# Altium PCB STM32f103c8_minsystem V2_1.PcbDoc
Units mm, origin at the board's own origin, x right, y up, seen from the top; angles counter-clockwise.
Board outline 18 x 35 mm, 2 copper layers (Top Layer, Bottom Layer); 27 components, 47 nets, 152 pads, 125 vias.
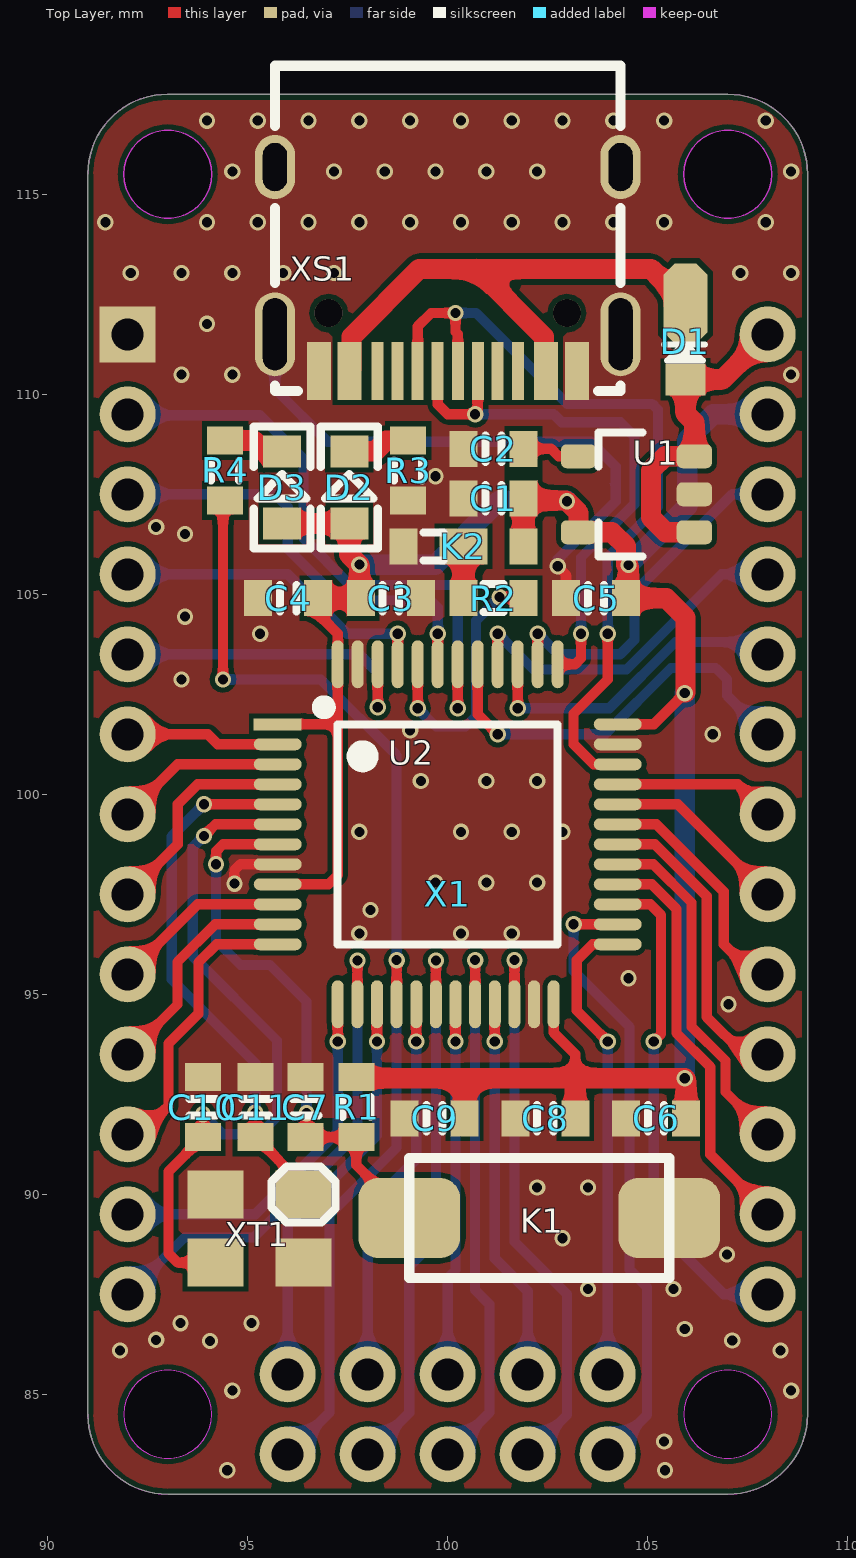
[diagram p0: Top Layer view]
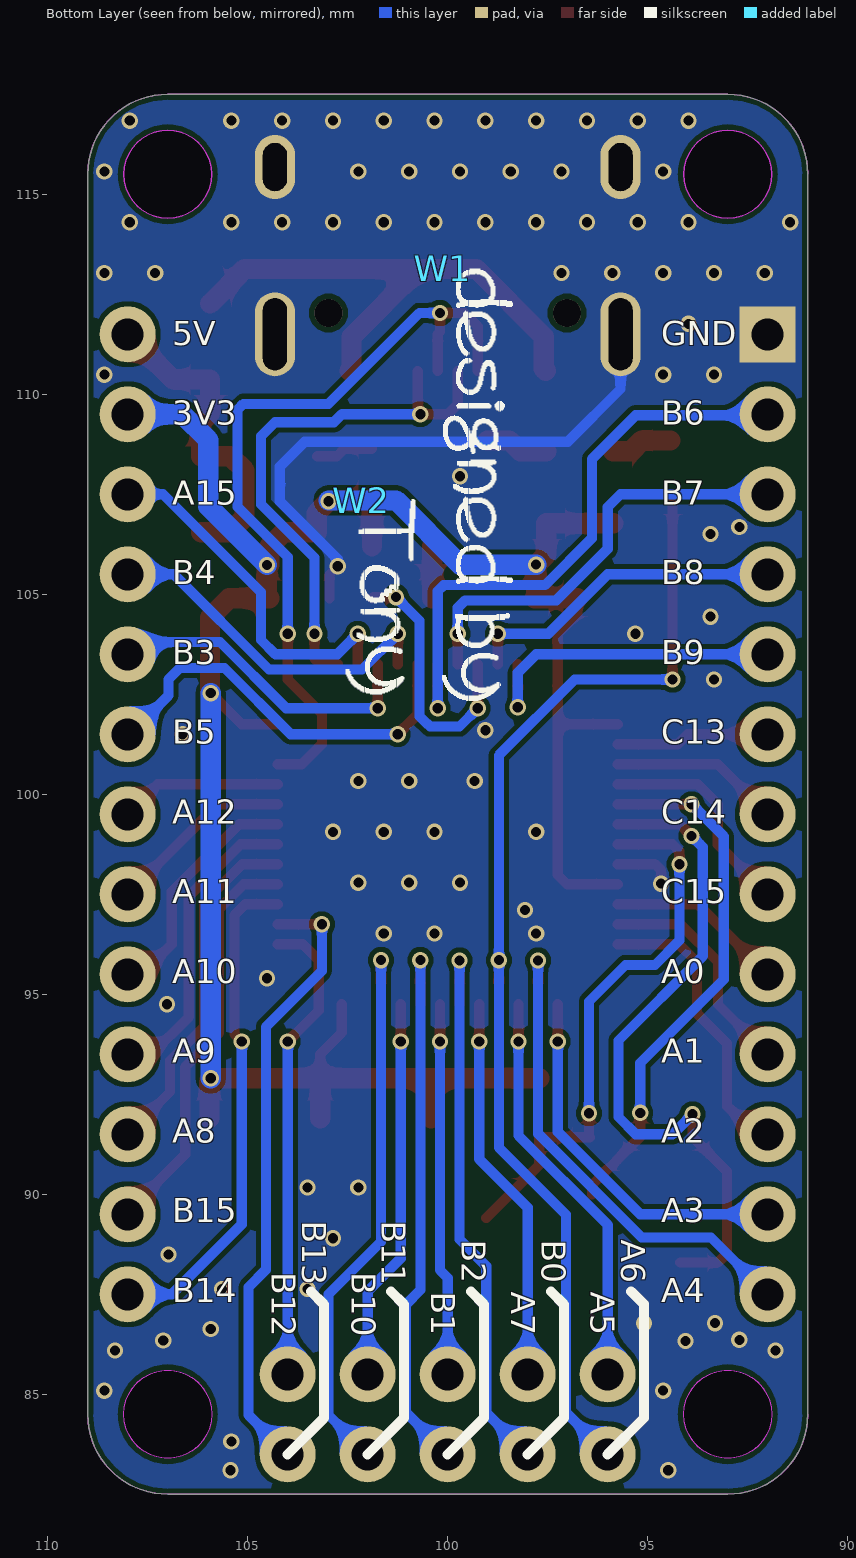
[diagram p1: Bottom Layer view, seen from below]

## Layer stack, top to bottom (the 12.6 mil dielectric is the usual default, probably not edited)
Top Solder: solder mask 0.0102, Solder Resist, Dk 3.5
Top Layer: signal copper 0.0356
Dielectric 1: dielectric 0.32, FR-4, Dk 4.8
Bottom Layer: signal copper 0.0356
Bottom Solder: solder mask 0.0102, Solder Resist, Dk 3.5

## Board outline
91,84.5 91,115.5 cw(c93,115.5) 93,117.5 107,117.5 cw(c107,115.5) 109,115.5 109,84.5 cw(c107,84.5) 107,82.5 93,82.5 cw(c93,84.5)
cut-out: 93,114.4 cw(c93,115.5) 91.9,115.5 cw(c93,115.5) 93,116.6 cw(c93,115.5) 94.1,115.5 cw(c93,115.5)
cut-out: 107,114.4 cw(c107,115.5) 105.9,115.5 cw(c107,115.5) 107,116.6 cw(c107,115.5) 108.1,115.5 cw(c107,115.5)
cut-out: 91.9,84.5 ccw(c93,84.5) 93,83.4 ccw(c93,84.5) 94.1,84.5 ccw(c93,84.5) 93,85.6 ccw(c93,84.5)
cut-out: 105.9,84.5 ccw(c107,84.5) 107,83.4 ccw(c107,84.5) 108.1,84.5 ccw(c107,84.5) 107,85.6 ccw(c107,84.5)

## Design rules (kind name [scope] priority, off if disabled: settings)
Clearance [All] p1: gap=0.127 ignorepadtopadclearanceinfootprint=TRUE
ComponentClearance [All] p1 off: gap=0 collisioncheckmode=3 verticalgap=0.254 showdistances=FALSE
PlaneConnect [All] p1: planeconnectstyle=Direct reliefexpansion=0.508 reliefentries=4 reliefconductorwidth=0.254 reliefairgap=0.254
PolygonConnect PolygonConnect_3 [All vs IsNamedPolygon('GND_L01_P001')] p1: connectstyle=Direct reliefconductorwidth=0.254 reliefentries=4 polygonreliefangle="90 Angle" airgapwidth=0.254
PolygonConnect PolygonConnect_2 [All vs IsNamedPolygon('GND_L02_P000')] p2: connectstyle=Direct reliefconductorwidth=0.254 reliefentries=4 polygonreliefangle="90 Angle" airgapwidth=0.254
PolygonConnect [All vs IsNamedPolygon('Bottom Layer-GND')] p3: connectstyle=Direct reliefconductorwidth=0.508 reliefentries=4 polygonreliefangle="90 Angle" airgapwidth=0.254
PolygonConnect PolygonConnect_1 [All vs IsNamedPolygon('Top Layer-GND')] p4: connectstyle=Direct reliefconductorwidth=0.508 reliefentries=4 polygonreliefangle="90 Angle" airgapwidth=0.254
RoutingVias [All] p1: holewidth=0.254 width=0.406 viastyle="Through Hole" minholewidth=0.254 minwidth=0.406 maxholewidth=0.711 maxwidth=1.27
SolderMaskExpansion [All] p1: expansion=0.102 istentingtop=FALSE
Width [All] p1: maxlimit=2.54 minlimit=0.254 preferedwidth=0.254
28 further rules are at their usual default settings.

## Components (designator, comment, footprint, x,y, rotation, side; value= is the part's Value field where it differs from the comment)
C1 "106" CAP_0603 101.143,107.779 r0 top locked
C2 "106" CAP_0603 101.143,109.017 r0 top locked
C3 "104" CAP_0603 98.577,104.521 r180 top locked
C4 "104" CAP_0603 96.012,104.521 r180 top locked
C5 "104" CAP_0603 103.708,105.283 r0 top locked
C6 "104" CAP_0603 105.207,92.278 r0 top locked
C7 "104" CAP_0603 96.063,92.177 r90 top locked
C8 "104" CAP_0603 102.438,92.278 r0 top locked
C9 "105" CAP_0603 99.67,92.278 r0 top locked
C10 "22p" CAP_0603 93.497,92.177 r90 top locked
C11 "22p" CAP_0603 94.818,92.177 r90 top locked
D1 "ss14" SOD-323 105.943,110.368 r90 top locked
D2 "led" led0603 97.663,107.721 r90 top locked
D3 "led" led0603 95.987,107.721 r90 top locked
K1 "3-6微动开关" 3-6微动开关 105.537,89.408 r180 top locked
K2 "Boot0选择-默认GND" "Switch 1-2 0603" 98.893,106.197 r0 top locked
R1 "10k" RES_0603 98.095,92.177 r270 top locked
R2 "10k" RES_0603 101.143,105.283 r0 top locked
R3 "3k" RES_0603 99.39,108.095 r270 top locked
R4 "3k" RES_0603 94.818,108.095 r270 top locked
U1 "ME6211 3V3" SOT23-5 104.667,107.5 r180 top locked
U2 "STM32F103C8T6" LQFP48 100,99 r0 top locked
W1 "设计于" "designed by（430-70）" 100.129,113.132 r270 bottom
W2 "Tony" Tony_2(200-70) 102.158,107.345 r270 bottom
X1 "STM32F103C8T6模块接口 V2.1" "STM32F103C8T6 V2_1引脚" 90,111.5 r0 top locked
XS1 "Type-C" TypeC-304-16BCP 95.68,111.5 r180 top locked
XT1 "8M" SMD3225_4p 96.393,89.99 r180 top locked

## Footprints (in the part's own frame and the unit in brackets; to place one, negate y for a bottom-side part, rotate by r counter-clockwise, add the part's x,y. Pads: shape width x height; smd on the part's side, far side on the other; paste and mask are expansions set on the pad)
3-6微动开关 [mm]
  rrect50% 2.54x2 smd: 1(0,0) 2(6.5,0)
  silkscreen extent 0,-1.5 6.5,1.5, body extent -0.9,-1.78 7.1,1.72, height 2.59
CAP_0603 [mm]
  rect 0.7x0.9 smd: 1(-0.75,-0.381) 2(0.75,-0.381)
  silkscreen extent -0.2,-0.71 0.2,-0.05, body extent -0.8,-0.78 0.8,0.02, height 0.8
"designed by（430-70）" [mm]
  silkscreen extent 0,0 10.79,1.75
led0603 [mm]
  rect 0.8x0.95 smd: 1(-0.95,0.125) 2(0.85,0.125)
  silkscreen extent -1.57,-0.59 1.47,0.84, body extent -1.02,-0.4 1,0.67, height 0.5
LQFP48 [mm] "STM32-48pin"
  rect 1.2x0.3 smd mask+0.051: 1(-4.25,2.75)
  oval 1.2x0.3 smd mask+0.051: 2(-4.25,2.25) 3(-4.25,1.75) 4(-4.25,1.25) 5(-4.25,0.75) 6(-4.25,0.25) 7(-4.25,-0.25) 8(-4.25,-0.75) 9(-4.25,-1.25) 10(-4.25,-1.75) 11(-4.25,-2.25) 12(-4.25,-2.75) 25(4.25,-2.75) 26(4.25,-2.25) 27(4.25,-1.75) 28(4.25,-1.25) 29(4.25,-0.75) 30(4.25,-0.25) 31(4.25,0.25) 32(4.25,0.75) 33(4.25,1.25) 34(4.25,1.75) 35(4.25,2.25) 36(4.25,2.75)
  oval 0.3x1.2 smd mask+0.051: 13(-2.75,-4.25) 14(-2.259,-4.25) 15(-1.768,-4.25) 16(-1.278,-4.25) 17(-0.787,-4.25) 18(-0.296,-4.25) 19(0.195,-4.25) 20(0.685,-4.25) 21(1.176,-4.25) 22(1.667,-4.25) 23(2.158,-4.25) 24(2.648,-4.25) 37(2.75,4.25) 38(2.25,4.25) 39(1.75,4.25) 40(1.25,4.25) 41(0.75,4.25) 42(0.25,4.25) 43(-0.25,4.25) 44(-0.75,4.25) 45(-1.25,4.25) 46(-1.75,4.25) 47(-2.25,4.25) 48(-2.75,4.25)
  silkscreen extent -3.25,-2.75 2.75,3.32, body extent -4.5,-4.5 4.5,4.5, height 1.45
RES_0603 [mm]
  rect 0.7x0.9 smd: 1(-0.75,-0.381) 2(0.75,-0.381)
  silkscreen extent -0.25,-0.73 0.25,-0.03, body extent -0.8,-0.78 0.8,0.02, height 0.45
SMD3225_4p [mm]
  rect 1.4x1.2 smd: 1(0,0) 2(2.2,0) 3(2.2,1.7) 4(0,1.7)
  silkscreen extent -0.8,-0.7 0.8,0.7, body extent -0.51,-0.41 2.69,2.09, height 0.81
SOD-323 [mm] "1.8x1.3X0.9mm（长宽高，不包括引脚）"
  oct 2x1.1 smd: 1(1.9,0)
  rect 0.8x1 smd: 2(0,0)
  silkscreen extent 0.47,-0.48 0.88,0.53, body extent -0.15,-0.67 2.5,0.62, height 1
SOT23-5 [mm] "SOT23, 3-Leads, Body 3.1x3.0mm (max), Pitch 0.95mm, IPC Medium Density"
  rrect50% 0.889x0.6 smd: 1(-1.5,0.95) 2(-1.5,0) 3(-1.5,-0.95) 4(1.396,-0.95) 5(1.396,0.95)
  silkscreen extent -0.2,-1.55 0.9,1.55, body extent -1.48,-1.45 1.32,1.45, height 1.2
"STM32F103C8T6 V2_1引脚" [mm] "排针朝下"
  rect 1.4x1.4 hole 0.8: 1(2,0)
  round 1.4 hole 0.8: 2(2,-2) 3(2,-4) 4(2,-6) 5(2,-8) 6(2,-10) 7(2,-12) 8(2,-14) 9(2,-16) 10(2,-18) 11(2,-20) 12(2,-22) 13(2,-24) 14(6,-26) 15(6,-28) 16(8,-26) 17(8,-28) 18(10,-26) 19(10,-28) 20(12,-26) 21(12,-28) 22(14,-26) 23(14,-28) 24(18,-24) 25(18,-22) 26(18,-20) 27(18,-18) 28(18,-16) 29(18,-14) 30(18,-12) 31(18,-10) 32(18,-8) 33(18,-6) 34(18,-4) 35(18,-2) 36(18,0)
  body extent 1,-29 19,1, height 1.8
"Switch 1-2 0603" [mm] "单刀双掷0603贴片选择开关"
  rect 0.7x0.9 smd: 1(0,0) 3(3,0)
  rect 1.2x0.9 smd: 2(1.5,0)
  silkscreen extent 0.5,-0.35 1,0.35, body extent -0.05,-0.4 1.55,0.4, height 0.45
Tony_2(200-70) [mm]
  silkscreen extent -0.03,-0.38 4.85,1.35
TypeC-304-16BCP [mm]
  oval 1x2.1 hole 0.6 slot 1.8 at 90 deg: 13(-8.64,0) 14(0,0)
  oval 1x1.6 hole 0.6 slot 1.2 at 90 deg: 15(-8.64,-4.18) 16(0,-4.18)
  rect 0.6x1.45 smd: A1B12(-7.545,0.915) A4B9(-6.77,0.915) B1A12(-1.1,0.915) B4A9(-1.87,0.915)
  rect 0.3x1.45 smd: A5(-5.57,0.914) A6(-4.57,0.915) A7(-4.07,0.915) A8(-3.07,0.915) B5(-2.57,0.915) B6(-3.57,0.915) B7(-5.07,0.915) B8(-6.07,0.915)
  round 0.7 hole 0.7 unplated: ""(-7.3,-0.53) ""(-1.34,-0.53)
  silkscreen extent -8.64,-6.71 0,1.42, body extent -8.77,-6.9 0.17,1, height 3.11

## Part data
C1 C2 C3 C4 C5 C6 C7 C8 C9 C10 C11: library part cap
D1: library part Diode
K1: "3*6mm"
K2: library part "Switch 1-2", "单刀双掷1-2"
R1 R2 R3 R4: library part Res
U1: library part ME6211, "LDO"
U2: library part STM32F103C8T6-LCC
XS1: library part Type-C母口
XT1: library part XTAL-4P

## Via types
v1: diameter 0.406, hole 0.254, Top Layer to Bottom Layer, 65 vias
v2: diameter 0.406, hole 0.254, Top Layer to Bottom Layer, tented both sides, 60 vias

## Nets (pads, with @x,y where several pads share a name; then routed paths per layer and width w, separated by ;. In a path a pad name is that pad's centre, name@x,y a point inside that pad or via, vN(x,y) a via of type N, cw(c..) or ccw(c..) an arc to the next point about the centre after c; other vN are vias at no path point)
3v3: C1.2 C3.2 C4.1 C5.2 C6.2 C8.2 C9.2 D2.1 D3.1 K2.3 R1.1 U1.5 U2.1 U2.9 U2.24 U2.36 U2.48 X1.35 | length 61.2
  Top Layer w0.254: U2.9 97.02,97.75 97.25,97.98 97.25,101.75 ; U2.1 97.25,101.75 ; C4.1 96.762,104.501 97.25,104.013 U2.48 97.25,101.75 ; U2.24 102.648,94.04 103.188,93.5 103.188,92.901 103.188,92.864 ; U2.36 105.148,101.75 v2(105.926,102.527) v2@105.943,102.545
  Top Layer w0.508: D3.1 D2.1 97.538,105.993 v2(97.79,105.74) 97.79,104.939 C3.2 C4.1 ; R1.1@97.714,92.901 100.432,92.901 ; C9.2 100.432,91.909 100.432,92.901 ; K2.3 C1.2 101.946,107.345 102.958,107.345 103.271,107.032 U1.5 104.106,106.55 104.458,106.197 v2@104.458,105.74 ; C8.2 103.188,92.864 ; v2(104.517,105.731) 104.517,104.961 C5.2 105.461,104.902 105.943,104.419 v2@105.943,102.545 ; C6.2 105.957,92.87 v2(105.926,92.901) 103.188,92.901 100.432,92.901
  Bottom Layer w0.508: v2(97.79,105.74) 99.688,105.74 101.293,107.345 v2@102.98,107.345 ; v2(104.517,105.731) 105.99,107.203 105.99,108.857 106.633,109.5 X1.35 ; v2(105.926,92.901) v2(105.926,102.527)
  other v2: 102.98,107.323
BOOT0: R2.2 U2.44 | length 6.7
  Top Layer w0.254: v2(99.25,102.151) U2.44 ; v2(101.295,104.927) 101.867,104.927 R2.2
  Bottom Layer w0.254: v2(99.25,102.151) 99.707,101.694 100.439,101.694 100.498,101.752 100.508,101.752 100.707,101.952 100.707,104.339 v2(101.295,104.927)
GND: C1.1 C2.1 C3.1 C4.2 C5.1 C6.1 C7.2 C8.1 C9.1 C10.2 C11.2 K1.1 K2.1 R3.2 U1.2 U2.8 U2.23 U2.35 U2.47 X1.1 XS1.13 XS1.14 XS1.15 XS1.16 XS1.A1B12 XS1.B1A12 XT1.2 XT1.4 | length 16.1
  Top Layer w0.254: v2(94.666,97.765) 94.666,98.101 94.815,98.25 U2.8 ; v2(102.75,105.7) 102.958,105.492 C5.1
  Bottom Layer w0.254: XS1.14 95.68,110.132 96.999,108.814 103.574,108.814 104.199,108.188 104.199,107.323 102.75,105.874 v2(102.75,105.7)
  other v1: 105.41,83.82 94.615,85.09 108.585,85.09 92.71,86.36 103.505,87.63 102.87,88.9 102.235,90.17 103.505,90.17 97.79,96.52 100.33,96.52 101.6,96.52 99.695,97.79 100.965,97.79 102.235,97.79 97.79,99.06 100.33,99.06 101.6,99.06 102.87,99.06 100.965,100.33 102.235,100.33 99.06,101.6 93.345,102.87 92.71,106.68 99.695,107.95 93.345,110.49 94.615,110.49 108.585,110.49 93.98,111.76 92.075,113.03 93.345,113.03 94.615,113.03 95.885,113.03 97.155,113.03 107.315,113.03 108.585,113.03 91.44,114.3 93.98,114.3 95.25,114.3 96.52,114.3 97.79,114.3 99.06,114.3 100.33,114.3 101.6,114.3 102.87,114.3 104.14,114.3 105.41,114.3 107.95,114.3 94.615,115.57 97.155,115.57 98.425,115.57 99.695,115.57 100.965,115.57 102.235,115.57 108.585,115.57 93.98,116.84 95.25,116.84 96.52,116.84 97.79,116.84 99.06,116.84 100.33,116.84 101.6,116.84 102.87,116.84 104.14,116.84 105.41,116.84 107.95,116.84
  other v2: 94.489,83.1 105.43,83.1 91.806,86.096 108.319,86.096 94.058,86.334 107.112,86.346 105.926,86.628 93.321,86.778 95.095,86.778 105.643,87.63 106.984,88.494 107.017,94.75 104.517,95.4 98.071,97.108 99.327,100.334 106.627,101.5 95.31,104.013 93.433,104.44 93.433,106.506
NetC2_2: C2.2 U1.4 | length 1.5
  Top Layer w0.254: C2.2 102.584,108.636 102.77,108.45 U1.4
NetC10_1: C10.1 U2.6 XT1.3 | length 17.3
  Top Layer w0.254: v2(93.878,91.999) C10.1 93.016,90.564 93.016,88.524 93.25,88.29 XT1.3 ; v2(93.904,98.958) 94.195,99.25 U2.6
  Bottom Layer w0.254: v2(93.878,91.999) 94.377,91.5 95.301,91.5 95.733,91.932 95.733,93.844 93.624,95.952 93.624,98.679 v2(93.904,98.958)
NetC11_1: C11.1 U2.5 XT1.1 | length 13.3
  Top Layer w0.254: v2(93.904,99.75) U2.5 ; v2(95.189,92.035) 95.189,91.437 96.393,90.233 XT1.1
  Bottom Layer w0.254: v2(93.904,99.75) 93.1,98.946 93.1,95.368 95.189,93.279 v2(95.189,92.035)
NetD1_1: D1.1 XS1.A4B9 XS1.B4A9 | length 13.5
  Top Layer w0.508: XS1.B4A9 97.596,110.631 97.596,111.437 99.29,113.132 100.708,113.132 ; XS1.A4B9 102.404,110.631 102.404,111.436 100.708,113.132 ; D1.1 105.08,113.132 100.708,113.132
NetD2_2: D2.2 R3.1 | length 1.6
  Top Layer w0.508: D2.2 98.185,108.571 98.459,108.845 R3.1
NetD3_2: D3.2 R4.1 | length 1.5
  Top Layer w0.508: R4.1 95.15,108.845 95.424,108.571 D3.2
NetK2_2: K2.2 R2.1 | length 1.3
  Top Layer w0.508: R2.1 K2.2
NRST: C7.1 K1.2 R1.2 U2.7 | length 14
  Top Layer w0.254: v2(94.209,98.25) 94.209,98.578 94.381,98.75 U2.7 ; v2(96.469,92.024) 96.469,91.452 C7.1 R1.2 97.714,90.731 K1.2
  Bottom Layer w0.254: v2(94.209,98.25) 94.209,96.342 94.818,95.733 95.555,95.733 96.469,94.818 v2(96.469,92.024)
PA0: U2.10 X1.9 | length 4.5
  Top Layer w0.254: X1.9 93.75,97.25 U2.10
PA1: U2.11 X1.10 | length 5.7
  Top Layer w0.254: X1.10 93.243,94.743 93.243,95.809 94.185,96.75 U2.11
PA2: U2.12 X1.11 | length 7.4
  Top Layer w0.254: X1.11 92.314,91.5 93.016,92.202 93.016,93.761 93.766,94.511 93.766,95.793 94.223,96.25 U2.12
PA3: U2.13 X1.12 | length 9.3
  Top Layer w0.254: v2(97.25,93.821) U2.13
  Bottom Layer w0.254: X1.12 95.189,89.5 97.25,91.561 v2(97.25,93.821)
PA4: U2.14 X1.13 | length 12.8
  Top Layer w0.254: U2.14 v2(97.741,95.843)
  Bottom Layer w0.254: X1.13 93.42,88.92 95.148,88.92 97.741,91.513 v2(97.741,95.843)
PA5: U2.15 X1.14 | length 10.2
  Top Layer w0.254: v2(98.232,93.821) U2.15
  Bottom Layer w0.254: X1.14 96,89.234 98.232,91.465 v2(98.232,93.821)
PA6: R4.2 U2.16 X1.15 | length 29.3
  Top Layer w0.254: v2(94.381,102.87) 94.381,107.289 R4.2 ; U2.16 v2(98.722,95.852)
  Bottom Layer w0.254: v2(94.381,102.87) 96.825,102.87 98.722,100.973 v2(98.722,95.852) 98.722,91.17 97.046,89.493 97.046,84.546 X1.15
PA7: U2.17 X1.16 | length 9.8
  Top Layer w0.254: v2(99.213,93.821) U2.17
  Bottom Layer w0.254: X1.16 98,89.665 99.213,90.878 v2(99.213,93.821)
PA8: U2.29 X1.26 | length 8.8
  Top Layer w0.254: U2.29 105.139,98.25 106.096,97.293 106.096,94.189 106.942,93.343 106.942,92.558 X1.26
PA9: U2.30 X1.27 | length 7.7
  Top Layer w0.254: U2.30 105.177,98.75 106.477,97.451 106.477,94.428 107.405,93.5 X1.27
PA10: U2.31 X1.28 | length 6.1
  Top Layer w0.254: U2.31 105.216,99.25 106.9,97.566 106.9,96.25 107.65,95.5 X1.28
PA11: U2.32 X1.29 | length 4.7
  Top Layer w0.254: U2.32 105.75,99.75 X1.29
PA12: U2.33 X1.30 | length 4.1
  Top Layer w0.254: U2.33 107.25,100.25 X1.30
PA15: U2.38 X1.34 | length 9.1
  Top Layer w0.254: U2.38 v2(102.25,104.013)
  Bottom Layer w0.254: v2(102.25,104.013) 102.763,103.5 104.309,103.5 104.667,103.857 104.667,105.05 107.117,107.5 X1.34
PB0: U2.18 X1.17 | length 14.1
  Top Layer w0.254: U2.18 v2(99.704,95.843)
  Bottom Layer w0.254: X1.17 99.037,84.537 99.037,88.204 99.704,88.871 v2(99.704,95.843)
PB1: U2.19 X1.18 | length 9.3
  Top Layer w0.254: v2(100.195,93.821) U2.19
  Bottom Layer w0.254: X1.18 100,87.908 100.195,88.103 v2(100.195,93.821)
PB2: U2.20 X1.19 | length 14
  Top Layer w0.254: U2.20 v2(100.685,95.852)
  Bottom Layer w0.254: X1.19 101.041,84.541 101.041,87.249 100.685,87.605 v2(100.685,95.852)
PB3: U2.39 X1.32 | length 8.2
  Top Layer w0.254: v2(101.75,102.151) U2.39
  Bottom Layer w0.254: v2(101.75,102.151) 104.038,102.151 105.693,103.806 107.694,103.806 X1.32
PB4: U2.40 X1.33 | length 8.9
  Top Layer w0.254: U2.40 v2(101.25,104.013)
  Bottom Layer w0.254: v2(101.25,104.013) 102.144,103.119 104.467,103.119 106.848,105.5 X1.33
PB5: U2.41 X1.31 | length 10.3
  Top Layer w0.254: U2.41 100.75,102 v2(101.25,101.5)
  Bottom Layer w0.254: v2(101.25,101.5) 103.926,101.5 105.582,103.156 106.698,103.156 106.984,102.87 106.984,102.466 107.95,101.5 X1.31
PB6: U2.42 X1.2 | length 15.3
  Top Layer w0.254: v2(100.25,102.151) U2.42
  Bottom Layer w0.254: X1.2 92.026,109.474 95.301,109.474 96.396,108.379 96.396,106.399 97.567,105.228 100.101,105.228 100.25,105.079 v2(100.25,102.151)
PB7: U2.43 X1.3 | length 10.9
  Top Layer w0.254: U2.43 v2(99.75,104.013)
  Bottom Layer w0.254: X1.3 95.68,107.5 96,107.18 96,106.136 97.289,104.847 99.566,104.847 99.75,104.663 v2(99.75,104.013)
PB8: U2.45 X1.4 | length 8.1
  Top Layer w0.254: U2.45 v2(98.75,104.013)
  Bottom Layer w0.254: X1.4 96,105.5 97.487,104.013 v2(98.75,104.013)
PB9: U2.46 X1.5 | length 8.4
  Top Layer w0.254: v2(98.25,102.176) U2.46
  Bottom Layer w0.254: X1.5 97.79,103.5 98.25,103.04 v2(98.25,102.176)
PB10: U2.21 X1.20 | length 9.6
  Top Layer w0.254: v2(101.176,93.821) U2.21
  Bottom Layer w0.254: v2(101.176,93.821) 101.176,88.399 102,87.575 X1.20
PB11: U2.22 X1.21 | length 14.4
  Top Layer w0.254: U2.22 v2(101.667,95.852)
  Bottom Layer w0.254: v2(101.667,95.852) 101.667,88.813 102.98,87.5 102.98,84.48 X1.21
PB12: U2.25 X1.22 | length 11.9
  Top Layer w0.254: v2(104,93.821) 103.225,94.596 103.225,95.852 103.623,96.25 U2.25
  Bottom Layer w0.254: X1.22 v2(104,93.821)
PB13: U2.26 X1.23 | length 15.5
  Top Layer w0.254: v2(103.148,96.75) U2.26
  Bottom Layer w0.254: v2(103.148,96.75) 103.148,95.582 104.546,94.183 104.546,88.113 104.978,87.681 104.978,84.478 X1.23
PB14: U2.27 X1.24 | length 12.6
  Top Layer w0.254: U2.27 105.061,97.25 105.334,96.977 105.334,94.005 v2(105.149,93.821) v2@105.105,93.777
  Bottom Layer w0.254: v2(105.149,93.821) 105.149,89.251 106.9,87.5 X1.24
PB15: U2.28 X1.25 | length 10.3
  Top Layer w0.254: U2.28 105.1,97.75 105.715,97.135 105.715,94.031 106.561,93.185 106.561,91 108,89.561 X1.25
PC13: U2.2 X1.6 | length 3.9
  Top Layer w0.254: X1.6 94,101.5 94.25,101.25 U2.2
PC14: U2.3 X1.7 | length 4.3
  Top Layer w0.254: X1.7 93.25,100.75 U2.3
PC15: U2.4 X1.8 | length 5.5
  Top Layer w0.254: X1.8 93.25,98.75 93.25,99.75 93.75,100.25 U2.4
SWCLK: U2.37 XS1.A7 XS1.B7 | length 13.9
  Top Layer w0.254: XS1.A7 99.75,109.75 100,109.5 v2(100.685,109.5) 100.75,109.565 XS1.B7 ; U2.37 103.185,103.25 103.333,103.399 v2(103.333,104.013)
  Bottom Layer w0.254: v2(100.685,109.5) 102.648,109.5 102.848,109.3 104.32,109.3 104.667,108.953 104.667,107.252 103.333,105.919 v2(103.333,104.013)
SWDIO: U2.34 XS1.A6 XS1.B6 | length 20.3
  Top Layer w0.254: XS1.B6 99.25,111.696 99.584,112.03 v2(100.195,112.03) 100.195,111.555 100.25,111.5 XS1.A6 ; v2(104,104.013) 104,102.87 103.148,102.018 103.148,101.25 103.648,100.75 U2.34
  Bottom Layer w0.254: v2(100.195,112.03) 100.71,112.03 102.98,109.76 105.109,109.76 105.257,109.612 105.257,107.189 104,105.932 v2(104,104.013)
VDD_5V: D1.2 U1.1 U1.3 X1.36 | length 8.2
  Top Layer w0.508: U1.1 105.453,106.55 105.08,106.923 105.08,108.095 105.435,108.45 U1.3 106.167,109.3 105.943,109.523 D1.2 106.868,110.368 X1.36
pads on no net: XS1. XS1.A5 XS1.A8 XS1.B5 XS1.B8

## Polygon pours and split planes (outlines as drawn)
GND on Bottom Layer "GND_L02_P000" (solid, remove dead copper, pour order 0): 91,82.5 109,82.5 109,117.5 91,117.5
GND on Top Layer "GND_L01_P001" (solid, remove dead copper, pour order 1): 91,82.5 109,82.5 109,117.5 91,117.5

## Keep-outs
Keep-Out Layer:
  circle w0.013: c93,115.5 r1.1
  circle w0.013: c107,115.5 r1.1
  circle w0.013: c107,84.5 r1.1
  circle w0.013: c93,84.5 r1.1
  lines w0.013: 91,84.5 ccw(c93,84.5) 93,82.5 107,82.5 ccw(c107,84.5) 109,84.5 109,115.5 ccw(c107,115.5) 107,117.5 93,117.5 ccw(c93,115.5) 91,115.5 91,84.5

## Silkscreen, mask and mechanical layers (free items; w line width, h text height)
Bottom Overlay:
  lines w0.254: 95.415,87.569 95.095,87.248 95.095,84.405 96.003,83.497 ; 97.417,87.567 97.096,87.247 97.096,84.404 98.005,83.495 ; 99.417,87.567 99.096,87.247 99.096,84.404 100.005,83.495 ; 101.417,87.567 101.096,87.247 101.096,84.404 102.005,83.495 ; 103.417,87.567 103.096,87.247 103.096,84.404 104.005,83.495
  text "GND" at 94.665,111.23 h0.6
  text "5V" at 106.886,111.23 h0.6
  text "B6" at 94.665,109.236 h0.6
  text "3V3" at 106.886,109.236 h0.6
  text "B7" at 94.665,107.242 h0.6
  text "A15" at 106.886,107.242 h0.6
  text "B8" at 94.665,105.248 h0.6
  text "B4" at 106.886,105.248 h0.6
  text "B9" at 94.665,103.255 h0.6
  text "B3" at 106.886,103.255 h0.6
  text "C13" at 94.665,101.261 h0.6
  text "B5" at 106.886,101.261 h0.6
  text "C14" at 94.665,99.267 h0.6
  text "A12" at 106.886,99.267 h0.6
  text "C15" at 94.665,97.273 h0.6
  text "A11" at 106.886,97.273 h0.6
  text "A0" at 94.665,95.279 h0.6
  text "A10" at 106.886,95.279 h0.6
  text "A1" at 94.665,93.285 h0.6
  text "A9" at 106.886,93.285 h0.6
  text "A2" at 94.665,91.291 h0.6
  text "A8" at 106.886,91.291 h0.6
  text "B11" at 101.644,89.342 h0.6 r90
  text "B13" at 103.638,89.342 h0.6 r90
  text "A3" at 94.665,89.297 h0.6
  text "B15" at 106.886,89.297 h0.6
  text "A6" at 95.662,88.864 h0.6 r90
  text "B0" at 97.656,88.864 h0.6 r90
  text "B2" at 99.65,88.864 h0.6 r90
  text "B10" at 102.406,88.047 h0.6 r90
  text "B12" at 104.4,88.047 h0.6 r90
  text "A5" at 96.424,87.569 h0.6 r90
  text "A7" at 98.418,87.569 h0.6 r90
  text "B1" at 100.412,87.569 h0.6 r90
  text "A4" at 94.665,87.303 h0.6
  text "B14" at 106.886,87.303 h0.6
Mechanical 1:
  circle w0.013: c93,115.5 r1.1
  circle w0.013: c107,115.5 r1.1
  circle w0.013: c107,84.5 r1.1
  circle w0.013: c93,84.5 r1.1
  lines w0.013: 91,84.5 ccw(c93,84.5) 93,82.5 107,82.5 ccw(c107,84.5) 109,84.5 109,115.5 ccw(c107,115.5) 107,117.5 93,117.5 ccw(c93,115.5) 91,115.5 91,84.5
